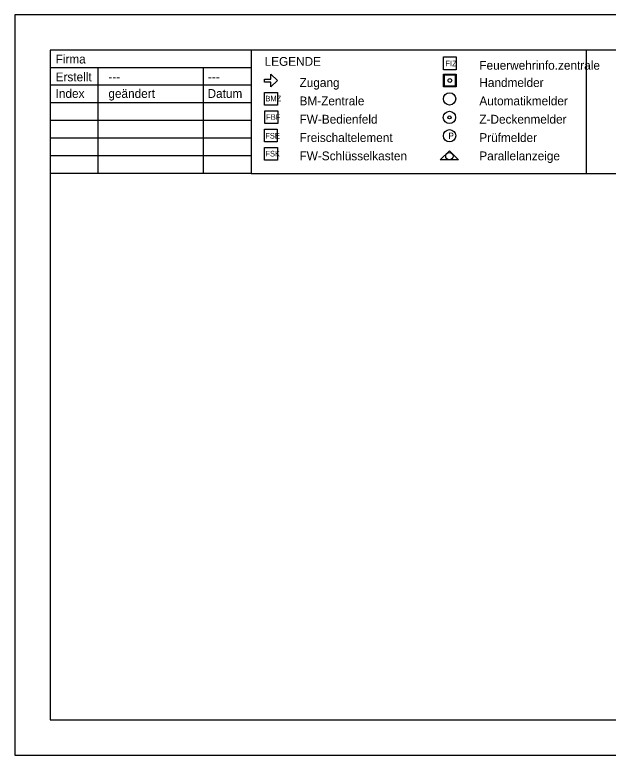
# Model space of a CAD drawing. Extents: x 0 to 29.7, y 0 to 21.
# Drawn here: x 0 to 16.82, y 0 to 21 of the extents above; entities that cross this region are included whole.
import ezdxf

# ---------------------------------------------------------------- set-up
doc = ezdxf.new("R2010")
doc.units = 0
doc.layers.add('90_Plankopf', color=7, linetype='Continuous')

msp = doc.modelspace()

# ---------------------------------------------------------------- linework, layer by layer
at = {"layer": '90_Plankopf'}
for p, q in [((16.2, 20), (16.2, 16.5)), ((6.7, 19.5), (1, 19.5)), ((2.362, 16.5), (2.362, 19.5)), ((5.347, 16.5), (5.347, 19.5)), ((6.7, 19), (1, 19)), ((6.7, 18.5), (1, 18.5)), ((6.7, 18), (1, 18)), ((6.7, 17.5), (1, 17.5)), ((12.062, 16.883), (12.321, 17.142)), ((12.581, 16.883), (12.321, 17.142)), ((6.7, 17), (1, 17)), ((12.581, 16.883), (12.062, 16.883)), ((6.7, 16.5), (1, 16.5))]:
    msp.add_line(p, q, dxfattribs=at)
for points in [[(0, 0), (29.7, 0), (29.7, 21), (0, 21)], [(28.7, 20), (1, 20), (1, 1), (28.7, 1)], [(28.7, 20), (6.7, 20), (6.7, 16.5), (28.7, 16.5)], [(12.154, 19.807), (12.518, 19.807), (12.518, 19.443), (12.154, 19.443)], [(7.263, 19.317), (7.445, 19.135), (7.263, 18.953), (7.263, 19.091), (7.081, 19.091), (7.081, 19.179), (7.263, 19.179)], [(12.154, 19.317), (12.514, 19.317), (12.514, 18.957), (12.154, 18.957)], [(12.174, 19.297), (12.494, 19.297), (12.494, 18.977), (12.174, 18.977)], [(7.083, 18.797), (7.447, 18.797), (7.447, 18.433), (7.083, 18.433)], [(7.09, 18.277), (7.454, 18.277), (7.454, 17.913), (7.09, 17.913)], [(7.079, 17.757), (7.443, 17.757), (7.443, 17.393), (7.079, 17.393)], [(7.083, 17.237), (7.447, 17.237), (7.447, 16.873), (7.083, 16.873)]]:
    msp.add_lwpolyline(points, close=True, dxfattribs=at)
msp.add_lwpolyline([(12.174, 18.977), (12.494, 18.977), (12.494, 19.297), (12.174, 19.297), (12.174, 18.977)], dxfattribs=at)
for centre, radius in [((12.334, 19.137), 0.054), ((12.334, 19.137), 0.054), ((12.328, 18.614), 0.175), ((12.328, 18.614), 0.175), ((12.324, 18.091), 0.175), ((12.324, 18.091), 0.175), ((12.324, 18.091), 0.0438), ((12.325, 17.571), 0.175), ((12.325, 17.571), 0.175), ((12.321, 16.991), 0.104), ((12.321, 16.991), 0.104)]:
    msp.add_circle(centre, radius, dxfattribs=at)

# ---------------------------------------------------------------- texts
for s, height, p in [('Firma', 0.25, (1.157, 19.62)), ('LEGENDE', 0.25, (7.082, 19.553)), ('FIZ', 0.1593, (12.21, 19.541)), ('Feuerwehrinfo.zentrale', 0.25, (13.171, 19.443)), ('Erstellt', 0.25, (1.157, 19.113)), ('---', 0.25, (2.653, 19.113)), ('---', 0.25, (5.475, 19.113)), ('Zugang', 0.25, (8.073, 18.953)), ('Handmelder', 0.25, (13.171, 18.953)), ('Index', 0.25, (1.157, 18.643)), ('geändert', 0.25, (2.653, 18.643)), ('Datum', 0.25, (5.465, 18.643)), ('BMZ', 0.1593, (7.104, 18.544)), ('BM-Zentrale', 0.25, (8.073, 18.433)), ('Automatikmelder', 0.25, (13.171, 18.433)), ('FBF', 0.1593, (7.125, 18.022)), ('FW-Bedienfeld', 0.25, (8.073, 17.913)), ('Z-Deckenmelder', 0.25, (13.171, 17.913)), ('FSE', 0.1593, (7.101, 17.49)), ('Freischaltelement', 0.25, (8.073, 17.393)), ('P', 0.175, (12.293, 17.482)), ('Prüfmelder', 0.25, (13.171, 17.393)), ('FSK', 0.1593, (7.104, 16.982)), ('FW-Schlüsselkasten', 0.25, (8.073, 16.873)), ('Parallelanzeige', 0.25, (13.171, 16.873))]:
    msp.add_text(s, height=height, dxfattribs=at).set_placement(p)

doc.saveas('drawing.dxf')
